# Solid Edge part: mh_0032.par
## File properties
Title: link
Author: edge
Template: normal.par
Last saved by: edge
Revision: 33
Application: Solid Edge
Material: ABS
非切断部品: False
文書内容のタイプ: 0
Density: 0.001200 g/mm^3
Accuracy: 0.99
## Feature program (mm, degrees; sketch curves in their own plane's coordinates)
sketch for "unnamed Protrusion 1" plane through (0, 0, 0) normal (0, 0, 1) x-axis (1, 0, 0)
  line (-5, 5) -> (5, 5)
  line (5, 5) -> (5, -35)
  line (5, -35) -> (-5, -35)
  line (-5, -35) -> (-5, 5)
extrude "unnamed Protrusion 1" add finite 1 symmetric
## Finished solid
Body 1: solid body, 6 faces, 12 edges, 8 vertices.
  Faces by surface: plane 6
  Edges by curve: line 12
Bounding box of the edges (mm): 10.000 x 40.000 x 1.000, from (-5, -35, -0.5) to (5, 5, 0.5).
Planar faces by outward normal: +x 1, +y 1, +z 1, -x 1, -y 1, -z 1
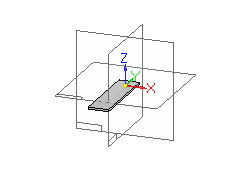
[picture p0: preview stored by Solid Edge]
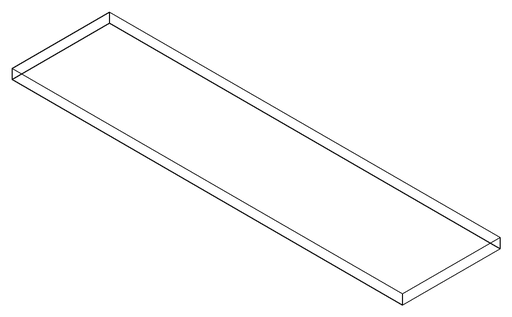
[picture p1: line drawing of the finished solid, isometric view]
